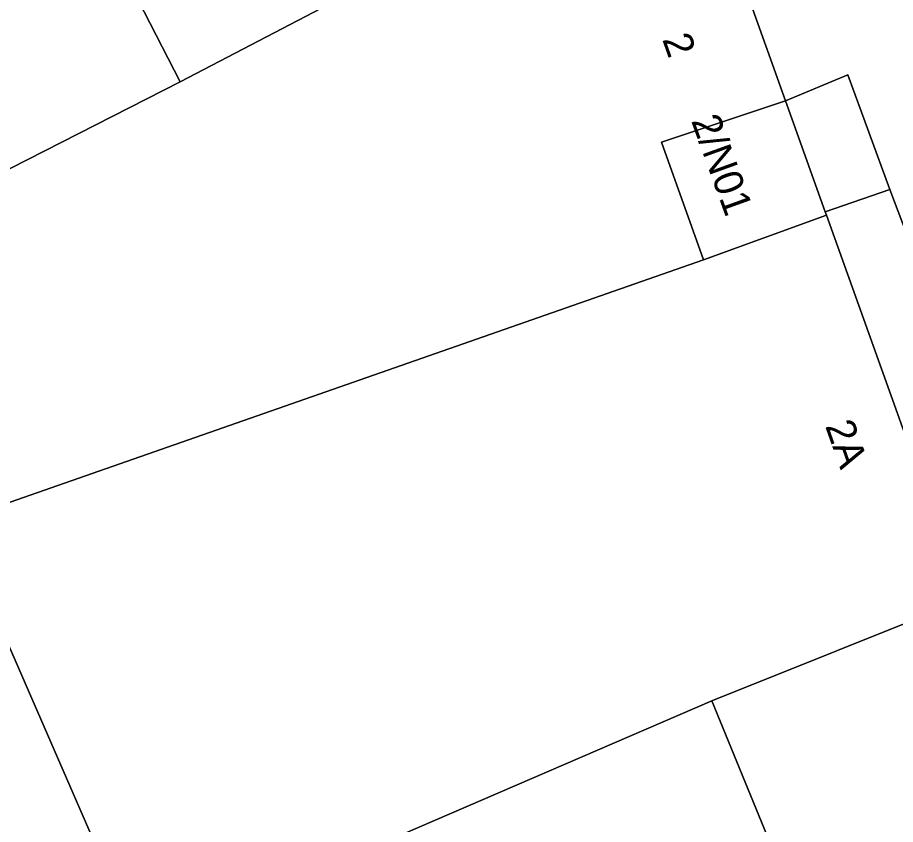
# Model space of a CAD drawing. Extents: x 158086 to 159499, y 382904 to 383981.
# Drawn here: x 158953.94 to 158984.21, y 383165.48 to 383193.31 of the extents above; entities that cross this region are included whole.
import ezdxf

# ---------------------------------------------------------------- set-up
doc = ezdxf.new("R2010")
doc.units = 0
for name, color, linetype in [('IMGEO_Erf', 7, 'Continuous'), ('IMGEO_Pand', 7, 'Continuous'), ('IMGEO_Pand_nummerreeks', 7, 'Continuous'), ('IMGEO_Voetpad_open', 7, 'Continuous')]:
    doc.layers.add(name, color=color, linetype=linetype)

msp = doc.modelspace()

# ---------------------------------------------------------------- linework, layer by layer
at = {"layer": 'IMGEO_Erf'}
msp.add_lwpolyline([(158891.196, 383156.515), (158899.184, 383160.496), (158901.092, 383161.447), (158897.978, 383167.788), (158908.666, 383173.037), (158909.107, 383172.139), (158912.826, 383173.965), (158915.457, 383168.606), (158916.311, 383166.642), (158924.709, 383170.295), (158931.701, 383173.336), (158931.332, 383174.141), (158930.271, 383176.45), (158934.478, 383178.529), (158931.303, 383184.932), (158931.168, 383185.203), (158936.642, 383187.918), (158939.952, 383181.235), (158947.827, 383185.128), (158959.542, 383191.092), (158957.677, 383194.726)], dxfattribs=at)
at = {"layer": 'IMGEO_Pand'}
for points in [[(158976.148, 383189.009), (158980.424, 383190.435), (158977.027, 383199.938), (158976.844, 383199.859), (158976.75, 383200.048), (158971.835, 383197.5), (158965.497, 383194.213), (158959.542, 383191.092), (158947.827, 383185.128), (158948.815, 383182.82), (158949.589, 383181.013), (158949.612, 383180.96), (158950.677, 383178.473), (158951.764, 383175.933), (158977.595, 383184.959)], [(158957.677, 383194.726), (158959.542, 383191.092), (158965.497, 383194.213), (158963.628, 383197.857)], [(158977.595, 383184.959), (158981.831, 383186.499), (158981.792, 383186.607), (158980.424, 383190.435), (158976.148, 383189.009)], [(158986.545, 383173.21), (158985.919, 383174.646), (158985.809, 383174.899), (158985.955, 383174.962), (158981.831, 383186.499), (158977.595, 383184.959), (158951.764, 383175.933), (158958.165, 383161.234), (158977.877, 383169.742)], [(158988.318, 383167.716), (158988.842, 383167.943), (158987.27, 383171.548), (158986.545, 383173.21), (158977.877, 383169.742), (158982.553, 383158.326), (158982.61, 383158.187), (158990.729, 383161.708), (158990.892, 383161.779)], [(158982.553, 383158.326), (158977.877, 383169.742), (158958.165, 383161.234), (158958.052, 383161.185), (158958.212, 383160.752), (158959.674, 383157.403), (158962.928, 383149.701), (158963.169, 383149.806), (158968.243, 383152.006), (158978.258, 383156.349), (158978.198, 383156.487)]]:
    msp.add_lwpolyline(points, close=True, dxfattribs=at)
msp.add_lwpolyline([(158958.165, 383161.234), (158951.764, 383175.933), (158950.677, 383178.473), (158949.612, 383180.96), (158949.589, 383181.013), (158948.815, 383182.82), (158947.827, 383185.128), (158939.952, 383181.235), (158934.478, 383178.529), (158930.271, 383176.45), (158931.332, 383174.141), (158931.701, 383173.336), (158932.903, 383170.718), (158936.265, 383163.395)], dxfattribs=at)
at = {"layer": 'IMGEO_Voetpad_open'}
for points in [[(158976.844, 383199.859), (158977.027, 383199.938), (158980.424, 383190.435), (158982.57, 383191.33), (158984.012, 383187.384), (158985.933, 383182.306), (158988.605, 383183.32), (158985.541, 383191.897), (158985.416, 383192.232), (158984.214, 383195.447), (158982.847, 383199.105), (158981.577, 383202.404), (158978.829, 383201.15), (158978.877, 383201.044), (158976.75, 383200.048)], [(158984.012, 383187.384), (158982.57, 383191.33), (158980.424, 383190.435), (158981.792, 383186.607)], [(158985.919, 383174.646), (158988.307, 383175.538), (158989.457, 383172.457), (158992.301, 383173.529), (158989.963, 383179.956), (158989.075, 383182.005), (158988.605, 383183.32), (158985.933, 383182.306), (158984.012, 383187.384), (158981.792, 383186.607), (158981.831, 383186.499), (158985.955, 383174.962), (158985.809, 383174.899)]]:
    msp.add_lwpolyline(points, close=True, dxfattribs=at)

# ---------------------------------------------------------------- texts
at = {"layer": 'IMGEO_Pand_nummerreeks'}
for s, rotation, p in [('2', 289.5147, (158976.161, 383192.563)), ('2/N01', 289.8552, (158977.159, 383189.755)), ('2A', 289.4746, (158981.779, 383179.227))]:
    msp.add_text(s, height=1, rotation=rotation, dxfattribs=at).set_placement(p)

doc.saveas('drawing.dxf')
